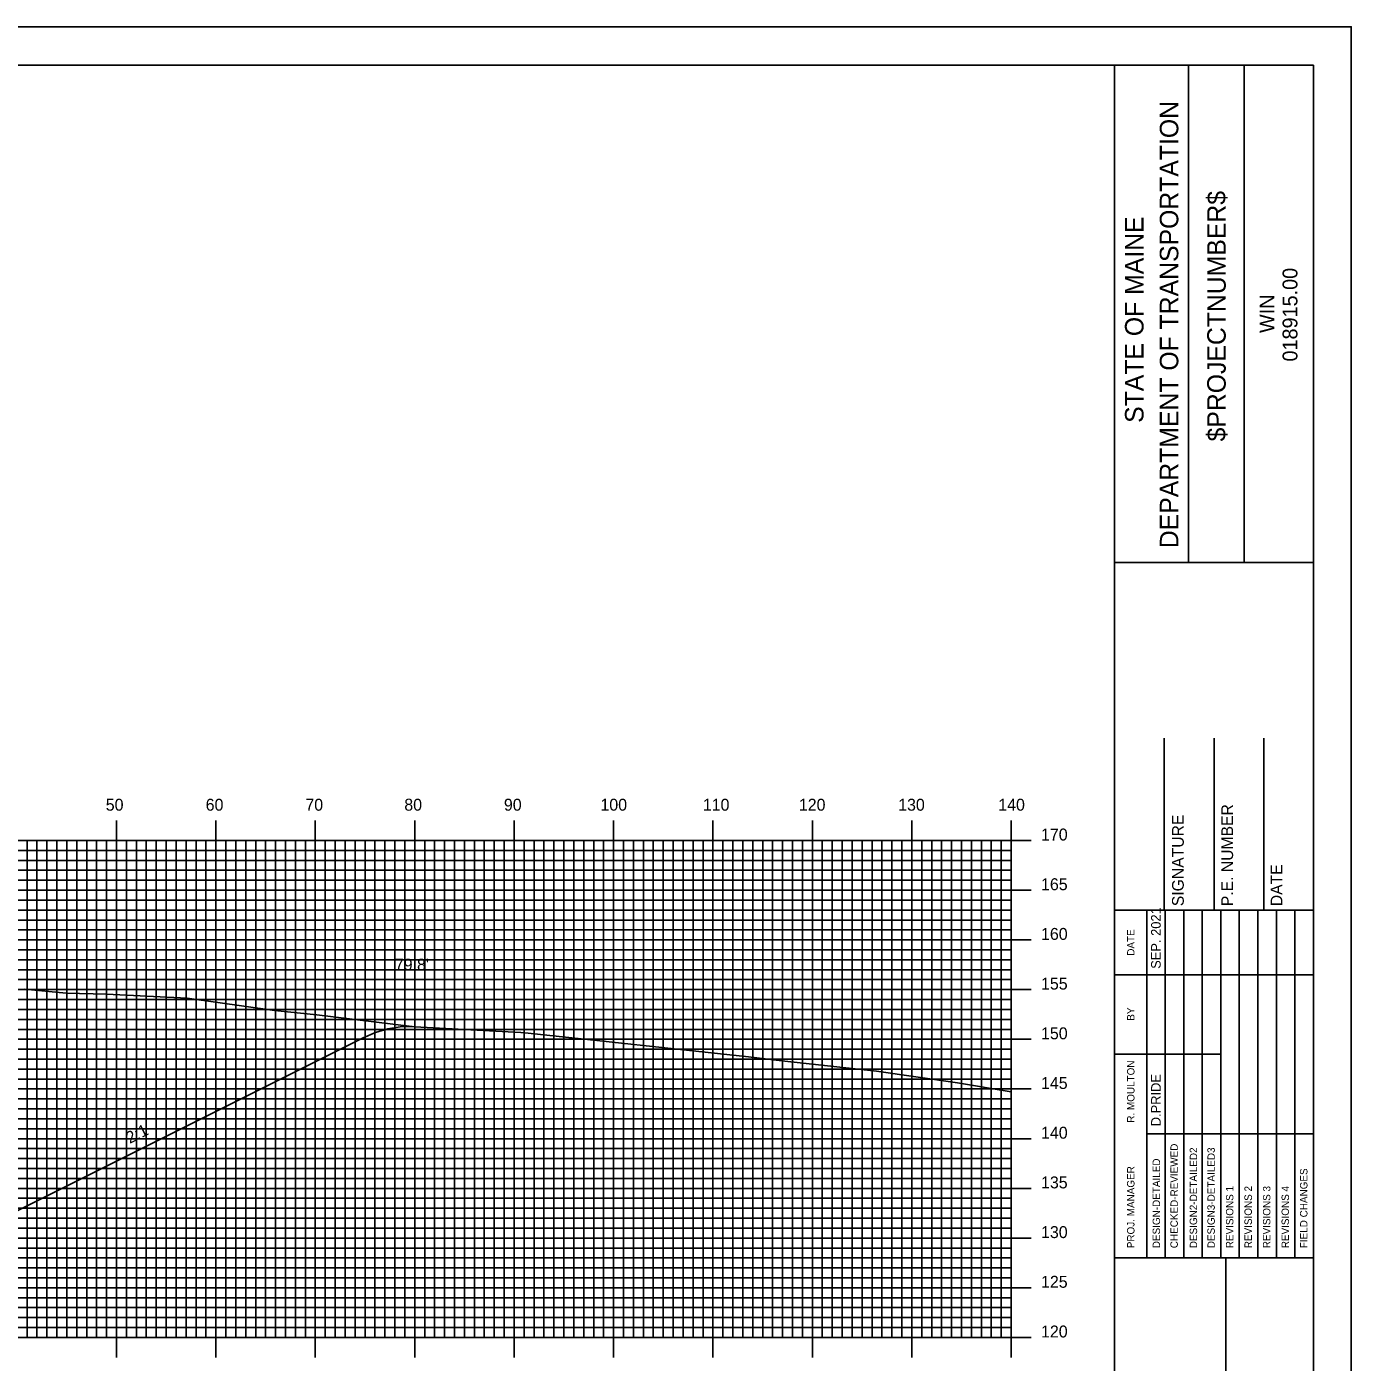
# Model space of a CAD drawing. Extents: x 1785008 to 1785352, y 442591 to 442811.
# Drawn here: x 1785215 to 1785348.2, y 442676.2 to 442810.5 of the extents above; entities that cross this region are included whole.
import ezdxf

# ---------------------------------------------------------------- set-up
doc = ezdxf.new("R2010")
doc.units = 0
for name, color, linetype in [('ANNOTATION', 7, 'Continuous'), ('BORDER', 7, 'Continuous'), ('D_Roadway_SlopeLines', 7, 'Continuous'), ('D_Text_Standard', 7, 'Continuous'), ('H_V ANNOTATION', 7, 'Continuous'), ('MAJOR', 7, 'Continuous'), ('MINOR', 7, 'Continuous'), ('PLOT BOUNDARY', 7, 'Continuous'), ('S_Roadway_Centerline', 7, 'Continuous')]:
    doc.layers.add(name, color=color, linetype=linetype)

msp = doc.modelspace()

# ---------------------------------------------------------------- linework, layer by layer
at = {"layer": 'BORDER'}
for p, q in [((1785324.43, 442596.67), (1785324.43, 442806.67)), ((1785331.88, 442756.66), (1785331.88, 442806.66)), ((1785337.47, 442756.66), (1785337.47, 442806.66)), ((1785324.43, 442756.65), (1785344.43, 442756.65)), ((1785324.43, 442756.65), (1785344.43, 442756.65)), ((1785329.43, 442721.67), (1785329.43, 442738.97)), ((1785329.43, 442721.67), (1785329.43, 442738.97)), ((1785334.43, 442721.67), (1785334.43, 442738.97)), ((1785334.43, 442721.67), (1785334.43, 442738.97)), ((1785339.43, 442721.67), (1785339.43, 442738.97)), ((1785339.43, 442721.67), (1785339.43, 442738.97)), ((1785324.43, 442721.67), (1785344.43, 442721.67)), ((1785324.43, 442721.67), (1785344.43, 442721.67)), ((1785324.43, 442686.67), (1785344.43, 442686.67)), ((1785324.43, 442686.67), (1785344.43, 442686.67)), ((1785335.61, 442616.67), (1785335.61, 442686.67)), ((1785335.61, 442616.67), (1785335.61, 442686.67))]:
    msp.add_line(p, q, dxfattribs=at)
msp.add_lwpolyline([(1785024.43, 442596.67), (1785344.43, 442596.67), (1785344.43, 442806.67), (1785024.43, 442806.67)], close=True, dxfattribs=at)
for points in [[(1785327.66, 442715.17), (1785327.66, 442721.67)], [(1785327.66, 442715.17), (1785327.66, 442721.67)], [(1785329.52, 442686.68), (1785329.52, 442721.67)], [(1785329.52, 442686.68), (1785329.52, 442721.67)], [(1785331.38, 442721.67), (1785331.38, 442686.68)], [(1785331.38, 442721.67), (1785331.38, 442686.68)], [(1785333.25, 442686.68), (1785333.25, 442721.67)], [(1785333.25, 442686.68), (1785333.25, 442721.67)], [(1785335.11, 442686.68), (1785335.11, 442721.67)], [(1785335.11, 442686.68), (1785335.11, 442721.67)], [(1785336.97, 442686.68), (1785336.97, 442721.67)], [(1785336.97, 442686.68), (1785336.97, 442721.67)], [(1785338.84, 442686.68), (1785338.84, 442721.67)], [(1785338.84, 442686.68), (1785338.84, 442721.67)], [(1785340.7, 442686.68), (1785340.7, 442721.67)], [(1785340.7, 442686.68), (1785340.7, 442721.67)], [(1785342.56, 442686.68), (1785342.56, 442721.67)], [(1785342.56, 442686.68), (1785342.56, 442721.67)], [(1785327.66, 442686.68), (1785327.66, 442720.26)], [(1785327.66, 442686.68), (1785327.66, 442720.26)], [(1785324.43, 442715.17), (1785344.43, 442715.17)], [(1785324.43, 442715.17), (1785344.43, 442715.17)], [(1785324.43, 442707.17), (1785327.66, 442707.17)], [(1785324.43, 442707.17), (1785327.66, 442707.17)], [(1785327.66, 442707.17), (1785335.11, 442707.17)], [(1785327.66, 442707.17), (1785335.11, 442707.17)], [(1785327.66, 442699.17), (1785344.43, 442699.17)], [(1785327.66, 442699.17), (1785344.43, 442699.17)]]:
    msp.add_lwpolyline(points, dxfattribs=at)
at = {"layer": 'D_Roadway_SlopeLines'}
msp.add_lwpolyline([(1785204.2, 442686.51), (1785248.83, 442708.82), (1785250.08, 442709.36), (1785251.33, 442709.73), (1785252.58, 442709.92), (1785253.83, 442709.94)], dxfattribs=at)
at = {"layer": 'MAJOR'}
for p, q in [((1785224.03, 442730.67), (1785224.03, 442728.67)), ((1785234.03, 442730.67), (1785234.03, 442728.67)), ((1785244.03, 442730.67), (1785244.03, 442728.67)), ((1785254.03, 442730.67), (1785254.03, 442728.67)), ((1785264.03, 442730.67), (1785264.03, 442728.67)), ((1785274.03, 442730.67), (1785274.03, 442728.67)), ((1785284.03, 442730.67), (1785284.03, 442728.67)), ((1785294.03, 442730.67), (1785294.03, 442728.67)), ((1785304.03, 442730.67), (1785304.03, 442728.67)), ((1785314.03, 442730.67), (1785314.03, 442728.67)), ((1785034.03, 442728.67), (1785314.03, 442728.67)), ((1785034.03, 442728.67), (1785314.03, 442728.67)), ((1785224.03, 442678.67), (1785224.03, 442728.67)), ((1785234.03, 442678.67), (1785234.03, 442728.67)), ((1785244.03, 442678.67), (1785244.03, 442728.67)), ((1785254.03, 442678.67), (1785254.03, 442728.67)), ((1785264.03, 442678.67), (1785264.03, 442728.67)), ((1785274.03, 442678.67), (1785274.03, 442728.67)), ((1785284.03, 442678.67), (1785284.03, 442728.67)), ((1785294.03, 442678.67), (1785294.03, 442728.67)), ((1785304.03, 442678.67), (1785304.03, 442728.67)), ((1785316.03, 442728.67), (1785312.02, 442728.67)), ((1785314.03, 442678.67), (1785314.03, 442728.67)), ((1785314.03, 442678.67), (1785314.03, 442728.67)), ((1785034.03, 442723.67), (1785314.03, 442723.67)), ((1785316.03, 442723.67), (1785312.02, 442723.67)), ((1785034.03, 442718.67), (1785314.03, 442718.67)), ((1785316.03, 442718.67), (1785312.02, 442718.67)), ((1785034.03, 442713.67), (1785314.03, 442713.67)), ((1785316.03, 442713.67), (1785312.02, 442713.67)), ((1785034.03, 442708.67), (1785314.03, 442708.67)), ((1785316.03, 442708.67), (1785312.02, 442708.67)), ((1785034.03, 442703.67), (1785314.03, 442703.67)), ((1785316.03, 442703.67), (1785312.02, 442703.67)), ((1785034.03, 442698.67), (1785314.03, 442698.67)), ((1785316.03, 442698.67), (1785312.02, 442698.67)), ((1785034.03, 442693.67), (1785314.03, 442693.67)), ((1785316.03, 442693.67), (1785312.02, 442693.67)), ((1785034.03, 442688.67), (1785314.03, 442688.67)), ((1785316.03, 442688.67), (1785312.02, 442688.67)), ((1785034.03, 442683.67), (1785314.03, 442683.67)), ((1785316.03, 442683.67), (1785312.02, 442683.67)), ((1785034.03, 442678.67), (1785314.03, 442678.67)), ((1785034.03, 442678.67), (1785314.03, 442678.67)), ((1785224.03, 442676.66), (1785224.03, 442678.67)), ((1785234.03, 442676.66), (1785234.03, 442678.67)), ((1785244.03, 442676.66), (1785244.03, 442678.67)), ((1785254.03, 442676.66), (1785254.03, 442678.67)), ((1785264.03, 442676.66), (1785264.03, 442678.67)), ((1785274.03, 442676.66), (1785274.03, 442678.67)), ((1785284.03, 442676.66), (1785284.03, 442678.67)), ((1785294.03, 442676.66), (1785294.03, 442678.67)), ((1785304.03, 442676.66), (1785304.03, 442678.67)), ((1785316.03, 442678.67), (1785312.02, 442678.67)), ((1785314.03, 442676.66), (1785314.03, 442678.67))]:
    msp.add_line(p, q, dxfattribs=at)
at = {"layer": 'MINOR'}
for p, q in [((1785215.03, 442678.67), (1785215.03, 442728.67)), ((1785216.03, 442678.67), (1785216.03, 442728.67)), ((1785217.03, 442678.67), (1785217.03, 442728.67)), ((1785218.03, 442678.67), (1785218.03, 442728.67)), ((1785219.03, 442678.67), (1785219.03, 442728.67)), ((1785220.03, 442678.67), (1785220.03, 442728.67)), ((1785221.03, 442678.67), (1785221.03, 442728.67)), ((1785222.03, 442678.67), (1785222.03, 442728.67)), ((1785223.03, 442678.67), (1785223.03, 442728.67)), ((1785225.03, 442678.67), (1785225.03, 442728.67)), ((1785226.03, 442678.67), (1785226.03, 442728.67)), ((1785227.03, 442678.67), (1785227.03, 442728.67)), ((1785228.03, 442678.67), (1785228.03, 442728.67)), ((1785229.03, 442678.67), (1785229.03, 442728.67)), ((1785230.03, 442678.67), (1785230.03, 442728.67)), ((1785231.03, 442678.67), (1785231.03, 442728.67)), ((1785232.03, 442678.67), (1785232.03, 442728.67)), ((1785233.03, 442678.67), (1785233.03, 442728.67)), ((1785235.03, 442678.67), (1785235.03, 442728.67)), ((1785236.03, 442678.67), (1785236.03, 442728.67)), ((1785237.03, 442678.67), (1785237.03, 442728.67)), ((1785238.03, 442678.67), (1785238.03, 442728.67)), ((1785239.03, 442678.67), (1785239.03, 442728.67)), ((1785240.03, 442678.67), (1785240.03, 442728.67)), ((1785241.03, 442678.67), (1785241.03, 442728.67)), ((1785242.03, 442678.67), (1785242.03, 442728.67)), ((1785243.03, 442678.67), (1785243.03, 442728.67)), ((1785245.03, 442678.67), (1785245.03, 442728.67)), ((1785246.03, 442678.67), (1785246.03, 442728.67)), ((1785247.03, 442678.67), (1785247.03, 442728.67)), ((1785248.03, 442678.67), (1785248.03, 442728.67)), ((1785249.03, 442678.67), (1785249.03, 442728.67)), ((1785250.03, 442678.67), (1785250.03, 442728.67)), ((1785251.03, 442678.67), (1785251.03, 442728.67)), ((1785252.03, 442678.67), (1785252.03, 442728.67)), ((1785253.03, 442678.67), (1785253.03, 442728.67)), ((1785255.03, 442678.67), (1785255.03, 442728.67)), ((1785256.03, 442678.67), (1785256.03, 442728.67)), ((1785257.03, 442678.67), (1785257.03, 442728.67)), ((1785258.03, 442678.67), (1785258.03, 442728.67)), ((1785259.03, 442678.67), (1785259.03, 442728.67)), ((1785260.03, 442678.67), (1785260.03, 442728.67)), ((1785261.03, 442678.67), (1785261.03, 442728.67)), ((1785262.03, 442678.67), (1785262.03, 442728.67)), ((1785263.03, 442678.67), (1785263.03, 442728.67)), ((1785265.03, 442678.67), (1785265.03, 442728.67)), ((1785266.03, 442678.67), (1785266.03, 442728.67)), ((1785267.03, 442678.67), (1785267.03, 442728.67)), ((1785268.03, 442678.67), (1785268.03, 442728.67)), ((1785269.03, 442678.67), (1785269.03, 442728.67)), ((1785270.03, 442678.67), (1785270.03, 442728.67)), ((1785271.03, 442678.67), (1785271.03, 442728.67)), ((1785272.03, 442678.67), (1785272.03, 442728.67)), ((1785273.03, 442678.67), (1785273.03, 442728.67)), ((1785275.03, 442678.67), (1785275.03, 442728.67)), ((1785276.03, 442678.67), (1785276.03, 442728.67)), ((1785277.03, 442678.67), (1785277.03, 442728.67)), ((1785278.03, 442678.67), (1785278.03, 442728.67)), ((1785279.03, 442678.67), (1785279.03, 442728.67)), ((1785280.03, 442678.67), (1785280.03, 442728.67)), ((1785281.03, 442678.67), (1785281.03, 442728.67)), ((1785282.03, 442678.67), (1785282.03, 442728.67)), ((1785283.03, 442678.67), (1785283.03, 442728.67)), ((1785285.03, 442678.67), (1785285.03, 442728.67)), ((1785286.03, 442678.67), (1785286.03, 442728.67)), ((1785287.03, 442678.67), (1785287.03, 442728.67)), ((1785288.03, 442678.67), (1785288.03, 442728.67)), ((1785289.03, 442678.67), (1785289.03, 442728.67)), ((1785290.03, 442678.67), (1785290.03, 442728.67)), ((1785291.03, 442678.67), (1785291.03, 442728.67)), ((1785292.03, 442678.67), (1785292.03, 442728.67)), ((1785293.03, 442678.67), (1785293.03, 442728.67)), ((1785295.03, 442678.67), (1785295.03, 442728.67)), ((1785296.03, 442678.67), (1785296.03, 442728.67)), ((1785297.03, 442678.67), (1785297.03, 442728.67)), ((1785298.03, 442678.67), (1785298.03, 442728.67)), ((1785299.03, 442678.67), (1785299.03, 442728.67)), ((1785300.03, 442678.67), (1785300.03, 442728.67)), ((1785301.03, 442678.67), (1785301.03, 442728.67)), ((1785302.03, 442678.67), (1785302.03, 442728.67)), ((1785303.03, 442678.67), (1785303.03, 442728.67)), ((1785305.03, 442678.67), (1785305.03, 442728.67)), ((1785306.03, 442678.67), (1785306.03, 442728.67)), ((1785307.03, 442678.67), (1785307.03, 442728.67)), ((1785308.03, 442678.67), (1785308.03, 442728.67)), ((1785309.03, 442678.67), (1785309.03, 442728.67)), ((1785310.03, 442678.67), (1785310.03, 442728.67)), ((1785311.03, 442678.67), (1785311.03, 442728.67)), ((1785312.03, 442678.67), (1785312.03, 442728.67)), ((1785313.03, 442678.67), (1785313.03, 442728.67)), ((1785034.03, 442727.67), (1785314.03, 442727.67)), ((1785314.03, 442727.67), (1785312.02, 442727.67)), ((1785034.03, 442726.67), (1785314.03, 442726.67)), ((1785314.03, 442726.67), (1785312.02, 442726.67)), ((1785034.03, 442725.67), (1785314.03, 442725.67)), ((1785034.03, 442724.67), (1785314.03, 442724.67)), ((1785314.03, 442725.67), (1785312.02, 442725.67)), ((1785314.03, 442724.67), (1785312.02, 442724.67)), ((1785034.03, 442722.67), (1785314.03, 442722.67)), ((1785314.03, 442722.67), (1785312.02, 442722.67)), ((1785034.03, 442721.67), (1785314.03, 442721.67)), ((1785034.03, 442720.67), (1785314.03, 442720.67)), ((1785314.03, 442721.67), (1785312.02, 442721.67)), ((1785314.03, 442720.67), (1785312.02, 442720.67)), ((1785034.03, 442719.67), (1785314.03, 442719.67)), ((1785314.03, 442719.67), (1785312.02, 442719.67)), ((1785034.03, 442717.67), (1785314.03, 442717.67)), ((1785034.03, 442716.67), (1785314.03, 442716.67)), ((1785314.03, 442717.67), (1785312.02, 442717.67)), ((1785314.03, 442716.67), (1785312.02, 442716.67)), ((1785034.03, 442715.67), (1785314.03, 442715.67)), ((1785314.03, 442715.67), (1785312.02, 442715.67)), ((1785034.03, 442714.67), (1785314.03, 442714.67)), ((1785314.03, 442714.67), (1785312.02, 442714.67)), ((1785034.03, 442712.67), (1785314.03, 442712.67)), ((1785314.03, 442712.67), (1785312.02, 442712.67)), ((1785034.03, 442711.67), (1785314.03, 442711.67)), ((1785314.03, 442711.67), (1785312.02, 442711.67)), ((1785034.03, 442710.67), (1785314.03, 442710.67)), ((1785314.03, 442710.67), (1785312.02, 442710.67)), ((1785034.03, 442709.67), (1785314.03, 442709.67)), ((1785314.03, 442709.67), (1785312.02, 442709.67)), ((1785034.03, 442707.67), (1785314.03, 442707.67)), ((1785314.03, 442707.67), (1785312.02, 442707.67)), ((1785034.03, 442706.67), (1785314.03, 442706.67)), ((1785314.03, 442706.67), (1785312.02, 442706.67)), ((1785034.03, 442705.67), (1785314.03, 442705.67)), ((1785034.03, 442704.67), (1785314.03, 442704.67)), ((1785314.03, 442705.67), (1785312.02, 442705.67)), ((1785314.03, 442704.67), (1785312.02, 442704.67)), ((1785034.03, 442702.67), (1785314.03, 442702.67)), ((1785314.03, 442702.67), (1785312.02, 442702.67)), ((1785034.03, 442701.67), (1785314.03, 442701.67)), ((1785034.03, 442700.67), (1785314.03, 442700.67)), ((1785314.03, 442701.67), (1785312.02, 442701.67)), ((1785314.03, 442700.67), (1785312.02, 442700.67)), ((1785034.03, 442699.67), (1785314.03, 442699.67)), ((1785314.03, 442699.67), (1785312.02, 442699.67)), ((1785034.03, 442697.67), (1785314.03, 442697.67)), ((1785034.03, 442696.67), (1785314.03, 442696.67)), ((1785314.03, 442697.67), (1785312.02, 442697.67)), ((1785314.03, 442696.67), (1785312.02, 442696.67)), ((1785034.03, 442695.67), (1785314.03, 442695.67)), ((1785314.03, 442695.67), (1785312.02, 442695.67)), ((1785034.03, 442694.67), (1785314.03, 442694.67)), ((1785314.03, 442694.67), (1785312.02, 442694.67)), ((1785034.03, 442692.67), (1785314.03, 442692.67)), ((1785314.03, 442692.67), (1785312.02, 442692.67)), ((1785034.03, 442691.67), (1785314.03, 442691.67)), ((1785314.03, 442691.67), (1785312.02, 442691.67)), ((1785034.03, 442690.67), (1785314.03, 442690.67)), ((1785034.03, 442689.67), (1785314.03, 442689.67)), ((1785314.03, 442690.67), (1785312.02, 442690.67)), ((1785314.03, 442689.67), (1785312.02, 442689.67)), ((1785034.03, 442687.67), (1785314.03, 442687.67)), ((1785314.03, 442687.67), (1785312.02, 442687.67)), ((1785034.03, 442686.67), (1785314.03, 442686.67)), ((1785034.03, 442685.67), (1785314.03, 442685.67)), ((1785314.03, 442686.67), (1785312.02, 442686.67)), ((1785314.03, 442685.67), (1785312.02, 442685.67)), ((1785034.03, 442684.67), (1785314.03, 442684.67)), ((1785314.03, 442684.67), (1785312.02, 442684.67)), ((1785034.03, 442682.67), (1785314.03, 442682.67)), ((1785034.03, 442681.67), (1785314.03, 442681.67)), ((1785314.03, 442682.67), (1785312.02, 442682.67)), ((1785314.03, 442681.67), (1785312.02, 442681.67)), ((1785034.03, 442680.67), (1785314.03, 442680.67)), ((1785314.03, 442680.67), (1785312.02, 442680.67)), ((1785034.03, 442679.67), (1785314.03, 442679.67)), ((1785314.03, 442679.67), (1785312.02, 442679.67))]:
    msp.add_line(p, q, dxfattribs=at)
at = {"layer": 'PLOT BOUNDARY'}
msp.add_lwpolyline([(1785008.24, 442590.55), (1785348.24, 442590.55), (1785348.24, 442810.55), (1785008.24, 442810.55)], close=True, dxfattribs=at)
at = {"layer": 'S_Roadway_Centerline'}
msp.add_lwpolyline([(1785214.79, 442713.7), (1785218.96, 442713.3), (1785223.01, 442713.22), (1785231.15, 442712.8), (1785239.92, 442711.57), (1785244.18, 442711.13), (1785254.02, 442709.92), (1785264.71, 442709.35), (1785265.45, 442709.28), (1785272.66, 442708.52), (1785287.6, 442706.9), (1785290.96, 442706.5), (1785300.48, 442705.45), (1785308.62, 442704.28), (1785314.03, 442703.39)], dxfattribs=at)

# ---------------------------------------------------------------- texts
at = {"layer": 'ANNOTATION'}
msp.add_text('2:1', height=1.2, rotation=26.5651, dxfattribs=at).set_placement((1785225.36, 442698.13))
at = {"layer": 'BORDER'}
for s, height, p in [('DEPARTMENT OF TRANSPORTATION', 1.8635, (1785330.84, 442758.08)), ('$PROJECTNUMBER$', 1.8635, (1785335.61, 442768.82)), ('STATE OF MAINE', 1.8635, (1785327.34, 442770.69)), ('018915.00', 1.491, (1785342.82, 442776.86)), ('WIN', 1.491, (1785340.5, 442779.73)), ('P.E. NUMBER', 1.1811, (1785336.35, 442722.06)), ('P.E. NUMBER', 1.1811, (1785336.35, 442722.06)), ('SIGNATURE', 1.181, (1785331.39, 442722.06)), ('SIGNATURE', 1.181, (1785331.39, 442722.06)), ('DATE', 1.181, (1785341.31, 442722.06)), ('DATE', 1.181, (1785341.31, 442722.06)), ('SEP. 2021', 0.969, (1785329.07, 442715.76)), ('DATE', 0.743, (1785326.43, 442717.08)), ('DATE', 0.743, (1785326.43, 442717.08)), ('BY', 0.743, (1785326.43, 442710.54)), ('BY', 0.743, (1785326.43, 442710.54)), ('R. MOULTON', 0.745, (1785326.43, 442700.28)), ('D.PRIDE', 0.969, (1785329.07, 442699.92)), ('CHECKED-REVIEWED', 0.7455, (1785330.79, 442687.65)), ('CHECKED-REVIEWED', 0.7455, (1785330.79, 442687.65)), ('DESIGN2-DETAILED2', 0.7455, (1785332.73, 442687.65)), ('DESIGN2-DETAILED2', 0.7455, (1785332.73, 442687.65)), ('DESIGN3-DETAILED3', 0.7455, (1785334.51, 442687.65)), ('DESIGN3-DETAILED3', 0.7455, (1785334.51, 442687.65)), ('DESIGN-DETAILED', 0.7455, (1785329, 442687.65)), ('DESIGN-DETAILED', 0.7455, (1785329, 442687.65)), ('PROJ. MANAGER', 0.7455, (1785326.43, 442687.65)), ('PROJ. MANAGER', 0.7455, (1785326.43, 442687.65)), ('FIELD CHANGES', 0.7455, (1785343.83, 442687.65)), ('FIELD CHANGES', 0.7455, (1785343.83, 442687.65)), ('REVISIONS 1', 0.7455, (1785336.38, 442687.65)), ('REVISIONS 1', 0.7455, (1785336.38, 442687.65)), ('REVISIONS 2', 0.7455, (1785338.24, 442687.65)), ('REVISIONS 2', 0.7455, (1785338.24, 442687.65)), ('REVISIONS 3', 0.7455, (1785340.1, 442687.65)), ('REVISIONS 3', 0.7455, (1785340.1, 442687.65)), ('REVISIONS 4', 0.7455, (1785341.97, 442687.65)), ('REVISIONS 4', 0.7455, (1785341.97, 442687.65))]:
    msp.add_text(s, height=height, rotation=90, dxfattribs=at).set_placement(p)
at = {"layer": 'D_Text_Standard'}
msp.add_text("79.8'", height=1.2, dxfattribs=at).set_placement((1785252.03, 442715.58))
at = {"layer": 'H_V ANNOTATION'}
for s, p in [('50', (1785222.95, 442731.67)), ('60', (1785233, 442731.67)), ('70', (1785243.03, 442731.67)), ('80', (1785252.98, 442731.67)), ('90', (1785263, 442731.67)), ('100', (1785272.71, 442731.67)), ('110', (1785283.01, 442731.67)), ('120', (1785292.67, 442731.67)), ('130', (1785302.66, 442731.67)), ('140', (1785312.73, 442731.67)), ('170', (1785317.03, 442728.67)), ('165', (1785317.03, 442723.67)), ('160', (1785317.03, 442718.67)), ('155', (1785317.03, 442713.67)), ('150', (1785317.03, 442708.67)), ('145', (1785317.03, 442703.67)), ('140', (1785317.03, 442698.67)), ('135', (1785317.03, 442693.67)), ('130', (1785317.03, 442688.67)), ('125', (1785317.03, 442683.67)), ('120', (1785317.03, 442678.67))]:
    msp.add_text(s, height=1.2, dxfattribs=at).set_placement(p)

doc.saveas('drawing.dxf')
